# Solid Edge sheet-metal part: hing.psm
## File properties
Author: Mac
Template: Normal.psm
Last saved by: Mac
Revision: 4
Application: Solid Edge
Density: 7750,000 kg/m^3
Accuracy: 0,990
Material Thickness: 0,04 mm
Bend Radius: 1,00 mm
Relief Width: 1,00 mm
Relief Length: 0,00 mm
Neutral Factor: 0,330
Minimum Arc Length: 0,10 mm
Deviational Tolerance: 0,10 mm
Material: Stainless steel
Face Style: Steel
Fill Style: ANSI32(Steel)
Virtual Style: Stainless steel
Coef. of Thermal Exp: 1.6e-05
Thermal Conductivity: 17.0
Specific Heat: 502.0
Modulus of Elasticity: 193053196000.0
Poission's Ratio: 0.29
Yield Stress: 310264065.0
Ultimate Stress: 641212401.0
Elongation: 0.0
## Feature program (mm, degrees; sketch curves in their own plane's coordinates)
base contour flange "ContourFlange_2"
sheet metal cutout "unnamed SheetMetalCutout 1"
break corner "BreakCorner_2"  SetBackValue1 = 0.08 mm
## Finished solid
Body 1: solid body, 28 faces, 74 edges, 48 vertices.
  Faces by surface: plane 18, cylinder 10
  Edges by curve: line 44, circle 30
Bounding box of the edges (mm): 1.015 x 1.200 x 0.180, from (-0.09, 0, 0) to (0.925, 1.2, 0.18).
Cylindrical faces by radius (mm): R0.05 x3, R0.06 x1, R0.08 x2, R0.09 x3, R0.1 x1
Planar faces by outward normal: +x 1, +y 3, +z 1, -y 4, -z 1, oblique 8
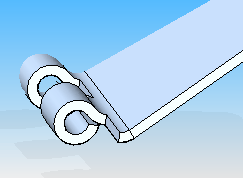
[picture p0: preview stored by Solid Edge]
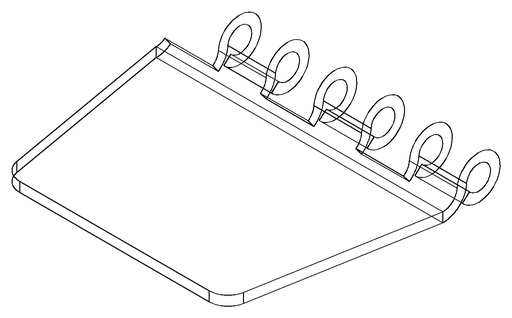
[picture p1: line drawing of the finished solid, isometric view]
